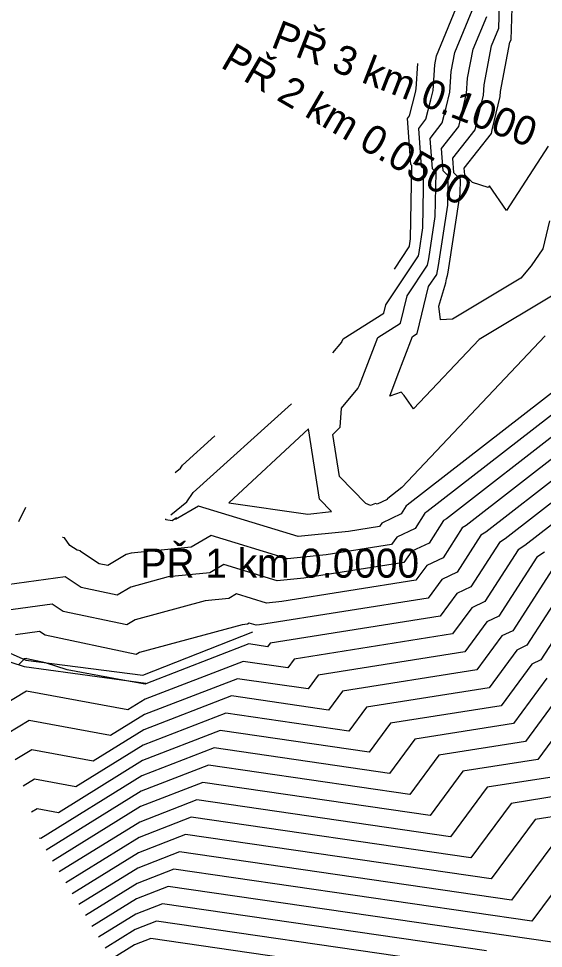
# Model space of a CAD drawing. Extents: x -549394 to -546608, y -1037055 to -1033629.
# Drawn here: x -548996.7 to -548832.9, y -1034491.4 to -1034201.2 of the extents above; entities that cross this region are included whole.
import ezdxf

# ---------------------------------------------------------------- set-up
doc = ezdxf.new("R2010")
doc.units = 0
for name, color, linetype in [('hlavni_vrst', 7, 'Continuous'), ('hrana_L', 7, 'Continuous'), ('norm_vrst', 7, 'Continuous'), ('x_popis_pricne_rezy_C122', 7, 'Continuous')]:
    doc.layers.add(name, color=color, linetype=linetype)

msp = doc.modelspace()

# ---------------------------------------------------------------- linework, layer by layer
at = {"layer": 'hlavni_vrst'}
for p, q in [((-548866.32, -1034212.87), (-548858.35, -1034193.59)), ((-548866.86, -1034215.66), (-548866.32, -1034212.87)), ((-548867.38, -1034223.67), (-548866.86, -1034215.66)), ((-548868.08, -1034226.59), (-548867.38, -1034223.67)), ((-548869.58, -1034232.66), (-548868.08, -1034226.59)), ((-548871.82, -1034235.53), (-548869.58, -1034232.66)), ((-548870.93, -1034247.44), (-548871.82, -1034235.53)), ((-548870.21, -1034248.15), (-548870.93, -1034247.44)), ((-548870.54, -1034266.47), (-548870.21, -1034248.15)), ((-548871.73, -1034274.18), (-548870.54, -1034266.47)), ((-548871.94, -1034275.3), (-548871.73, -1034274.18)), ((-548882.1, -1034290.56), (-548871.94, -1034275.3)), ((-548882.72, -1034293.1), (-548882.1, -1034290.56)), ((-548895.44, -1034301.16), (-548882.72, -1034293.1)), ((-548898.62, -1034305.55), (-548895.85, -1034302.2)), ((-548895.85, -1034302.2), (-548895.81, -1034302.13)), ((-548895.81, -1034302.13), (-548895.44, -1034301.16)), ((-548827.23, -1034315.61), (-548875.4, -1034353.08)), ((-548942.26, -1034349.1), (-548911.49, -1034321.45)), ((-548791.42, -1034322), (-548844.83, -1034363.54)), ((-548906.26, -1034329.26), (-548931.06, -1034352.35)), ((-548902.78, -1034351.17), (-548906.26, -1034329.26)), ((-548944.23, -1034352.06), (-548942.26, -1034349.1)), ((-548949.17, -1034356.03), (-548944.23, -1034352.06)), ((-548931.06, -1034352.35), (-548906.47, -1034355.85)), ((-548899.05, -1034354.99), (-548902.78, -1034351.17)), ((-548940.52, -1034353.34), (-548947.76, -1034357.55)), ((-548909.51, -1034362.87), (-548940.52, -1034353.34)), ((-548906.47, -1034355.85), (-548899.05, -1034354.99)), ((-548875.73, -1034353.29), (-548877.34, -1034355.79)), ((-548875.4, -1034353.08), (-548875.73, -1034353.29)), ((-548950.73, -1034357.6), (-548950.77, -1034357.3)), ((-548948.77, -1034357.93), (-548950.73, -1034357.6)), ((-548947.43, -1034357.02), (-548948.77, -1034357.93)), ((-548947.76, -1034357.55), (-548947.43, -1034357.02)), ((-548877.34, -1034355.79), (-548883.32, -1034358.63)), ((-548893.78, -1034361.24), (-548909.51, -1034362.87)), ((-548884.11, -1034359.7), (-548893.78, -1034361.24)), ((-548883.32, -1034358.63), (-548884.11, -1034359.7)), ((-548844.83, -1034363.54), (-548846.62, -1034364.71)), ((-548846.62, -1034364.71), (-548855.54, -1034378.56)), ((-548855.54, -1034378.56), (-548859.96, -1034380.65)), ((-548817.51, -1034376.13), (-548833.75, -1034401.33)), ((-548859.96, -1034380.65), (-548865.11, -1034387.66)), ((-548865.11, -1034387.66), (-548918.22, -1034396.08)), ((-548918.22, -1034396.08), (-548919.06, -1034397.21)), ((-548924.84, -1034396.37), (-548956.96, -1034408.78)), ((-548919.06, -1034397.21), (-548924.84, -1034396.37)), ((-548995.14, -1034401.33), (-548996.72, -1034402.87)), ((-548995.12, -1034401.14), (-548995.14, -1034401.33)), ((-548994.93, -1034400.98), (-548995.12, -1034401.14)), ((-548994.6, -1034401), (-548994.93, -1034400.98)), ((-548994.18, -1034400.94), (-548994.6, -1034401)), ((-548994.08, -1034401.01), (-548994.18, -1034400.94)), ((-548988.34, -1034402.23), (-548994.08, -1034401.01)), ((-548833.75, -1034401.33), (-548836.59, -1034402.68)), ((-548981.56, -1034404.41), (-548988.34, -1034402.23)), ((-548964.19, -1034407.61), (-548981.56, -1034404.41)), ((-548836.59, -1034402.68), (-548846.11, -1034415.62)), ((-548957.17, -1034408.91), (-548964.19, -1034407.61)), ((-548956.96, -1034408.78), (-548957.17, -1034408.91)), ((-548846.11, -1034415.62), (-548880.61, -1034421.09)), ((-548880.61, -1034421.09), (-548887.34, -1034430.14)), ((-548933.84, -1034423.41), (-548958, -1034432.75)), ((-548887.34, -1034430.14), (-548933.84, -1034423.41)), ((-548958, -1034432.75), (-548984.28, -1034449)), ((-548827.11, -1034443.57), (-548843, -1034446.09)), ((-548990.91, -1034447.77), (-548992.7, -1034448.85)), ((-548984.28, -1034449), (-548990.91, -1034447.77)), ((-548843, -1034446.09), (-548855.62, -1034463.08)), ((-548942.84, -1034450.45), (-548959.04, -1034456.71)), ((-548855.62, -1034463.08), (-548942.84, -1034450.45)), ((-548959.04, -1034456.71), (-548981.97, -1034470.89)), ((-548951.84, -1034477.49), (-548960.08, -1034480.67)), ((-548850.73, -1034492.13), (-548951.84, -1034477.49)), ((-548960.08, -1034480.67), (-548971.75, -1034487.89))]:
    msp.add_line(p, q, dxfattribs=at)
at = {"layer": 'hrana_L'}
for p, q in [((-548957.94, -1034406.11), (-548923.56, -1034392.53)), ((-549008.6, -1034395.1), (-548994.42, -1034401.45)), ((-549008.01, -1034399.22), (-548994.94, -1034403.44)), ((-548994.42, -1034401.45), (-548957.94, -1034406.11)), ((-548994.94, -1034403.44), (-548956.95, -1034408.59))]:
    msp.add_line(p, q, dxfattribs=at)
at = {"layer": 'norm_vrst'}
for p, q in [((-548860.59, -1034211.8), (-548854.44, -1034196.95)), ((-548846.84, -1034204.2), (-548846.61, -1034196.78)), ((-548843.05, -1034207.82), (-548842.74, -1034197.92)), ((-548854.85, -1034210.74), (-548850.64, -1034200.57)), ((-548849.11, -1034209.68), (-548846.84, -1034204.2)), ((-548851.44, -1034221.91), (-548849.11, -1034209.68)), ((-548846.3, -1034223.99), (-548843.38, -1034208.62)), ((-548843.38, -1034208.62), (-548843.05, -1034207.82)), ((-548861.72, -1034217.74), (-548860.59, -1034211.8)), ((-548856.58, -1034219.83), (-548854.85, -1034210.74)), ((-548872.62, -1034223.19), (-548872.1, -1034215.26)), ((-548862.13, -1034224.14), (-548861.72, -1034217.74)), ((-548856.89, -1034224.61), (-548856.58, -1034219.83)), ((-548851.65, -1034225.08), (-548851.44, -1034221.91)), ((-548874.68, -1034231.56), (-548872.88, -1034224.27)), ((-548872.88, -1034224.27), (-548872.62, -1034223.19)), ((-548863.28, -1034228.92), (-548862.13, -1034224.14)), ((-548858.48, -1034231.24), (-548856.89, -1034224.61)), ((-548853.68, -1034233.57), (-548851.65, -1034225.08)), ((-548846.41, -1034225.55), (-548846.3, -1034223.99)), ((-548848.88, -1034235.89), (-548846.41, -1034225.55)), ((-548864.48, -1034233.77), (-548863.28, -1034228.92)), ((-548875.37, -1034232.45), (-548874.68, -1034231.56)), ((-548874.29, -1034246.8), (-548875.37, -1034232.45)), ((-548868.28, -1034238.62), (-548864.48, -1034233.77)), ((-548859.38, -1034234.87), (-548858.48, -1034231.24)), ((-548854.28, -1034235.97), (-548853.68, -1034233.57)), ((-548864.73, -1034241.71), (-548859.38, -1034234.87)), ((-548861.18, -1034244.79), (-548854.28, -1034235.97)), ((-548849.18, -1034237.08), (-548848.88, -1034235.89)), ((-548867.56, -1034248.07), (-548868.28, -1034238.62)), ((-548857.63, -1034247.88), (-548849.18, -1034237.08)), ((-548864.2, -1034248.71), (-548864.73, -1034241.71)), ((-548831.41, -1034241.01), (-548844.45, -1034261.12)), ((-548860.84, -1034249.35), (-548861.18, -1034244.79)), ((-548874.41, -1034270), (-548873.99, -1034247.1)), ((-548873.99, -1034247.1), (-548874.29, -1034246.8)), ((-548866.43, -1034249.21), (-548867.56, -1034248.07)), ((-548857.47, -1034249.98), (-548857.63, -1034247.88)), ((-548866.68, -1034262.95), (-548866.43, -1034249.21)), ((-548862.65, -1034250.26), (-548864.2, -1034248.71)), ((-548862.81, -1034259.42), (-548862.65, -1034250.26)), ((-548858.86, -1034251.32), (-548860.84, -1034249.35)), ((-548855.08, -1034252.37), (-548857.47, -1034249.98)), ((-548858.95, -1034255.9), (-548858.86, -1034251.32)), ((-548855.08, -1034252.37), (-548855.08, -1034252.37)), ((-548855.08, -1034252.37), (-548855.08, -1034252.37)), ((-548855.08, -1034252.37), (-548855.08, -1034252.37)), ((-548855.08, -1034252.37), (-548855.08, -1034252.37)), ((-548850.22, -1034253.88), (-548855.08, -1034252.37)), ((-548855.08, -1034252.37), (-548855.08, -1034252.37)), ((-548849.79, -1034253.41), (-548850.22, -1034253.88)), ((-548844.45, -1034261.12), (-548849.79, -1034253.41)), ((-548862.71, -1034280.36), (-548858.95, -1034255.9)), ((-548865.72, -1034278.3), (-548862.81, -1034259.42)), ((-548868.72, -1034276.24), (-548866.68, -1034262.95)), ((-548831.06, -1034264.29), (-548833.16, -1034273.12)), ((-548874.74, -1034272.12), (-548874.41, -1034270)), ((-548879.45, -1034279.42), (-548874.8, -1034272.43)), ((-548874.8, -1034272.43), (-548874.74, -1034272.12)), ((-548833.16, -1034273.12), (-548836.75, -1034278.35)), ((-548869.09, -1034278.17), (-548868.72, -1034276.24)), ((-548875.43, -1034287.69), (-548869.09, -1034278.17)), ((-548866.23, -1034281.04), (-548865.72, -1034278.3)), ((-548836.75, -1034278.35), (-548840.02, -1034282.27)), ((-548868.75, -1034284.82), (-548866.23, -1034281.04)), ((-548863.42, -1034283.68), (-548863.13, -1034282.4)), ((-548863.13, -1034282.4), (-548862.91, -1034281.41)), ((-548862.91, -1034281.41), (-548862.71, -1034280.36)), ((-548840.02, -1034282.27), (-548861.35, -1034295.02)), ((-548872.31, -1034299.46), (-548868.75, -1034284.82)), ((-548865.62, -1034290.94), (-548863.42, -1034283.68)), ((-548877.51, -1034296.28), (-548875.43, -1034287.69)), ((-548828.91, -1034286.91), (-548852.99, -1034301.31)), ((-548865.07, -1034295.2), (-548865.62, -1034290.94)), ((-548884.61, -1034300.78), (-548877.51, -1034296.28)), ((-548861.35, -1034295.02), (-548865.07, -1034295.2)), ((-548878.58, -1034312.93), (-548873.78, -1034300.39)), ((-548832.35, -1034300.26), (-548877.14, -1034347.58)), ((-548873.78, -1034300.39), (-548872.31, -1034299.46)), ((-548890.28, -1034315.6), (-548884.61, -1034300.78)), ((-548852.99, -1034301.31), (-548873.52, -1034323.01)), ((-548799.8, -1034301.11), (-548869.29, -1034355.17)), ((-548797.7, -1034306.33), (-548863.17, -1034357.27)), ((-548795.61, -1034311.56), (-548857.06, -1034359.36)), ((-548880.89, -1034319.06), (-548878.58, -1034312.93)), ((-548895.92, -1034322.78), (-548890.89, -1034316.7)), ((-548890.89, -1034316.7), (-548890.28, -1034315.6)), ((-548877.34, -1034317.84), (-548880.89, -1034319.06)), ((-548876.4, -1034318.81), (-548877.34, -1034317.84)), ((-548793.52, -1034316.78), (-548850.94, -1034361.45)), ((-548873.52, -1034323.01), (-548876.4, -1034318.81)), ((-548896.31, -1034328.69), (-548895.92, -1034322.78)), ((-548898.6, -1034331.03), (-548896.31, -1034328.69)), ((-548789.33, -1034327.22), (-548838.71, -1034365.64)), ((-548945.53, -1034340.53), (-548935.41, -1034331.44)), ((-548896.52, -1034344.11), (-548898.6, -1034331.03)), ((-548946.18, -1034341.51), (-548945.53, -1034340.53)), ((-548947.8, -1034342.82), (-548946.18, -1034341.51)), ((-548888.3, -1034352.54), (-548896.52, -1034344.11)), ((-548877.14, -1034347.58), (-548881.52, -1034350.99)), ((-548886.88, -1034353.16), (-548888.3, -1034352.54)), ((-548885.35, -1034352.57), (-548886.88, -1034353.16)), ((-548884.83, -1034352.73), (-548885.35, -1034352.57)), ((-548881.69, -1034351.24), (-548884.83, -1034352.73)), ((-548881.55, -1034351.01), (-548881.69, -1034351.24)), ((-548881.52, -1034350.99), (-548881.55, -1034351.01)), ((-548996.66, -1034358.1), (-548994.4, -1034353.67)), ((-548869.9, -1034355.58), (-548872.98, -1034360.34)), ((-548869.29, -1034355.17), (-548869.9, -1034355.58)), ((-548864.08, -1034357.86), (-548868.62, -1034364.9)), ((-548863.17, -1034357.27), (-548864.08, -1034357.86)), ((-548872.98, -1034360.34), (-548878.65, -1034363.04)), ((-548858.26, -1034360.14), (-548864.26, -1034369.45)), ((-548857.06, -1034359.36), (-548858.26, -1034360.14)), ((-548850.94, -1034361.45), (-548852.44, -1034362.43)), ((-548982.93, -1034363.12), (-548982.82, -1034362.98)), ((-548982.38, -1034363.25), (-548982.93, -1034363.12)), ((-548980.67, -1034365.6), (-548982.38, -1034363.25)), ((-548936.57, -1034362.48), (-548942.86, -1034366.13)), ((-548912.78, -1034369.79), (-548936.57, -1034362.48)), ((-548878.65, -1034363.04), (-548880.31, -1034365.29)), ((-548852.44, -1034362.43), (-548859.9, -1034374)), ((-548980.67, -1034365.6), (-548980.68, -1034365.62)), ((-548978.45, -1034367.12), (-548980.68, -1034365.62)), ((-548977.35, -1034367.27), (-548978.45, -1034367.12)), ((-548942.86, -1034366.13), (-548961.6, -1034367.99)), ((-548880.31, -1034365.29), (-548900.72, -1034368.53)), ((-548868.62, -1034364.9), (-548873.98, -1034367.44)), ((-548840.79, -1034366.99), (-548851.18, -1034383.11)), ((-548838.71, -1034365.64), (-548840.79, -1034366.99)), ((-548977.38, -1034367.51), (-548977.35, -1034367.27)), ((-548971.54, -1034371.36), (-548977.38, -1034367.51)), ((-548963.12, -1034368.4), (-548968.87, -1034371.92)), ((-548961.6, -1034367.99), (-548963.12, -1034368.4)), ((-548900.72, -1034368.53), (-548912.78, -1034369.79)), ((-548873.98, -1034367.44), (-548876.51, -1034370.89)), ((-548864.26, -1034369.45), (-548869.31, -1034371.85)), ((-548834.97, -1034369.28), (-548846.83, -1034387.66)), ((-548832.6, -1034367.73), (-548834.97, -1034369.28)), ((-548968.87, -1034371.92), (-548971.54, -1034371.36)), ((-548932.61, -1034371.61), (-548936.99, -1034374.16)), ((-548916.06, -1034376.7), (-548932.61, -1034371.61)), ((-548876.51, -1034370.89), (-548907.66, -1034375.82)), ((-548869.31, -1034371.85), (-548872.71, -1034376.48)), ((-548829.15, -1034371.56), (-548842.47, -1034392.22)), ((-548982.2, -1034375.46), (-549003.72, -1034378.43)), ((-548977.17, -1034378.77), (-548982.2, -1034375.46)), ((-548950.03, -1034375.45), (-548961.72, -1034378.59)), ((-548936.99, -1034374.16), (-548950.03, -1034375.45)), ((-548907.66, -1034375.82), (-548916.06, -1034376.7)), ((-548859.9, -1034374), (-548864.63, -1034376.25)), ((-548823.33, -1034373.85), (-548838.11, -1034396.77)), ((-548965.92, -1034381.16), (-548977.17, -1034378.77)), ((-548961.72, -1034378.59), (-548965.92, -1034381.16)), ((-548872.71, -1034376.48), (-548914.6, -1034383.12)), ((-548864.63, -1034376.25), (-548868.91, -1034382.07)), ((-548928.66, -1034380.75), (-548931.13, -1034382.18)), ((-548919.34, -1034383.61), (-548928.66, -1034380.75)), ((-548986.19, -1034383.96), (-549000.68, -1034385.96)), ((-548982.81, -1034386.18), (-548986.19, -1034383.96)), ((-548938.47, -1034382.91), (-548960.32, -1034388.78)), ((-548931.13, -1034382.18), (-548938.47, -1034382.91)), ((-548868.91, -1034382.07), (-548921.55, -1034390.41)), ((-548914.6, -1034383.12), (-548919.34, -1034383.61)), ((-548851.18, -1034383.11), (-548855.29, -1034385.06)), ((-548962.96, -1034390.4), (-548982.81, -1034386.18)), ((-548855.29, -1034385.06), (-548861.31, -1034393.25)), ((-548960.32, -1034388.78), (-548962.96, -1034390.4)), ((-548926.91, -1034390.37), (-548958.92, -1034398.98)), ((-548925.26, -1034390.2), (-548926.91, -1034390.37)), ((-548924.71, -1034389.88), (-548925.26, -1034390.2)), ((-548922.61, -1034390.53), (-548924.71, -1034389.88)), ((-548921.55, -1034390.41), (-548922.61, -1034390.53)), ((-548850.61, -1034389.46), (-548857.51, -1034398.84)), ((-548846.83, -1034387.66), (-548850.61, -1034389.46)), ((-548990.19, -1034392.45), (-548997.64, -1034393.48)), ((-548988.45, -1034393.59), (-548990.19, -1034392.45)), ((-548861.31, -1034393.25), (-548910.7, -1034401.08)), ((-548842.47, -1034392.22), (-548845.94, -1034393.87)), ((-548960.01, -1034399.64), (-548988.45, -1034393.59)), ((-548845.94, -1034393.87), (-548853.71, -1034404.43)), ((-548958.92, -1034398.98), (-548960.01, -1034399.64)), ((-548857.51, -1034398.84), (-548903.18, -1034406.08)), ((-548841.27, -1034398.27), (-548849.91, -1034410.03)), ((-548838.11, -1034396.77), (-548841.27, -1034398.27)), ((-548926.64, -1034401.78), (-548957.17, -1034413.57)), ((-548912.71, -1034403.79), (-548926.64, -1034401.78)), ((-548910.7, -1034401.08), (-548912.71, -1034403.79)), ((-548853.71, -1034404.43), (-548895.65, -1034411.08)), ((-548928.44, -1034407.19), (-548957.37, -1034418.37)), ((-548906.37, -1034410.38), (-548928.44, -1034407.19)), ((-548903.18, -1034406.08), (-548906.37, -1034410.38)), ((-548831.92, -1034407.08), (-548842.31, -1034421.21)), ((-548849.91, -1034410.03), (-548888.13, -1034416.09)), ((-548994.25, -1034411.06), (-549002.77, -1034416.2)), ((-548962.59, -1034416.93), (-548994.25, -1034411.06)), ((-548957.17, -1034413.57), (-548962.59, -1034416.93)), ((-548930.24, -1034412.59), (-548957.58, -1034423.16)), ((-548900.02, -1034416.97), (-548930.24, -1034412.59)), ((-548895.65, -1034411.08), (-548900.02, -1034416.97)), ((-548827.25, -1034411.48), (-548838.51, -1034426.8)), ((-548888.13, -1034416.09), (-548893.68, -1034423.56)), ((-548822.58, -1034415.89), (-548834.71, -1034432.39)), ((-548957.37, -1034418.37), (-548968.01, -1034424.95)), ((-548932.04, -1034418), (-548957.79, -1034427.95)), ((-548893.68, -1034423.56), (-548932.04, -1034418)), ((-548993.41, -1034420.24), (-549000.25, -1034424.36)), ((-548968.01, -1034424.95), (-548993.41, -1034420.24)), ((-548842.31, -1034421.21), (-548873.09, -1034426.09)), ((-548957.58, -1034423.16), (-548973.44, -1034432.96)), ((-548957.79, -1034427.95), (-548978.86, -1034440.98)), ((-548873.09, -1034426.09), (-548880.99, -1034436.73)), ((-548838.51, -1034426.8), (-548865.57, -1034431.09)), ((-548992.58, -1034429.41), (-548997.74, -1034432.52)), ((-548973.44, -1034432.96), (-548992.58, -1034429.41)), ((-548935.64, -1034428.82), (-548958.21, -1034437.54)), ((-548880.99, -1034436.73), (-548935.64, -1034428.82)), ((-548865.57, -1034431.09), (-548874.65, -1034443.32)), ((-548834.71, -1034432.39), (-548858.04, -1034436.09)), ((-548937.44, -1034434.22), (-548958.42, -1034442.33)), ((-548874.65, -1034443.32), (-548937.44, -1034434.22)), ((-548858.04, -1034436.09), (-548868.3, -1034449.91)), ((-548991.75, -1034438.59), (-548995.22, -1034440.69)), ((-548978.86, -1034440.98), (-548991.75, -1034438.59)), ((-548958.21, -1034437.54), (-548989.7, -1034457.02)), ((-548939.24, -1034439.63), (-548958.62, -1034447.12)), ((-548868.3, -1034449.91), (-548939.24, -1034439.63)), ((-548830.91, -1034437.98), (-548850.52, -1034441.09)), ((-548958.42, -1034442.33), (-548988.11, -1034460.7)), ((-548850.52, -1034441.09), (-548861.96, -1034456.49)), ((-548941.04, -1034445.04), (-548958.83, -1034451.92)), ((-548861.96, -1034456.49), (-548941.04, -1034445.04)), ((-548958.62, -1034447.12), (-548986.06, -1034464.09)), ((-548835.48, -1034451.1), (-548849.27, -1034469.67)), ((-548823.31, -1034449.17), (-548835.48, -1034451.1)), ((-548958.83, -1034451.92), (-548984.02, -1034467.49)), ((-548990.08, -1034456.95), (-548990.18, -1034457.01)), ((-548989.7, -1034457.02), (-548990.08, -1034456.95)), ((-548944.64, -1034455.86), (-548959.25, -1034461.5)), ((-548849.27, -1034469.67), (-548944.64, -1034455.86)), ((-548827.96, -1034456.1), (-548842.93, -1034476.26)), ((-548959.25, -1034461.5), (-548979.93, -1034474.29)), ((-548946.44, -1034461.26), (-548959.46, -1034466.3)), ((-548842.93, -1034476.26), (-548946.44, -1034461.26)), ((-548820.43, -1034461.1), (-548836.58, -1034482.84)), ((-548959.46, -1034466.3), (-548977.88, -1034477.69)), ((-548948.24, -1034466.67), (-548959.67, -1034471.09)), ((-548836.58, -1034482.84), (-548948.24, -1034466.67)), ((-548959.67, -1034471.09), (-548975.84, -1034481.09)), ((-548950.04, -1034472.08), (-548959.87, -1034475.88)), ((-548830.24, -1034489.43), (-548950.04, -1034472.08)), ((-548959.87, -1034475.88), (-548973.8, -1034484.49)), ((-548953.64, -1034482.9), (-548960.29, -1034485.47)), ((-548872.05, -1034494.71), (-548953.64, -1034482.9)), ((-548960.29, -1034485.47), (-548969.71, -1034491.29)), ((-548955.44, -1034488.3), (-548960.5, -1034490.26)), ((-548893.37, -1034497.29), (-548955.44, -1034488.3)), ((-548960.5, -1034490.26), (-548967.66, -1034494.69))]:
    msp.add_line(p, q, dxfattribs=at)

# ---------------------------------------------------------------- texts
at = {"layer": 'x_popis_pricne_rezy_C122'}
for s, rotation, p in [('PŘ 3 km 0.1000', 338.7363, (-548918.31, -1034209.97)), ('PŘ 2 km 0.0500', 329.8345, (-548934.02, -1034216.27))]:
    msp.add_text(s, height=9.0627, rotation=rotation, dxfattribs=at).set_placement(p)
msp.add_text('PŘ 1 km 0.0000', height=9.0627, dxfattribs=at).set_placement((-548958.64, -1034375.67))

doc.saveas('drawing.dxf')
